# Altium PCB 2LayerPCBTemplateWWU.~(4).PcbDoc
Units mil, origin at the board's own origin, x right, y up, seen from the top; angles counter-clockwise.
Board outline 958.19 x 1191.13 mil, 2 copper layers (Top Layer, Bottom Layer); 9 components, 9 nets, 39 pads, 16 vias.
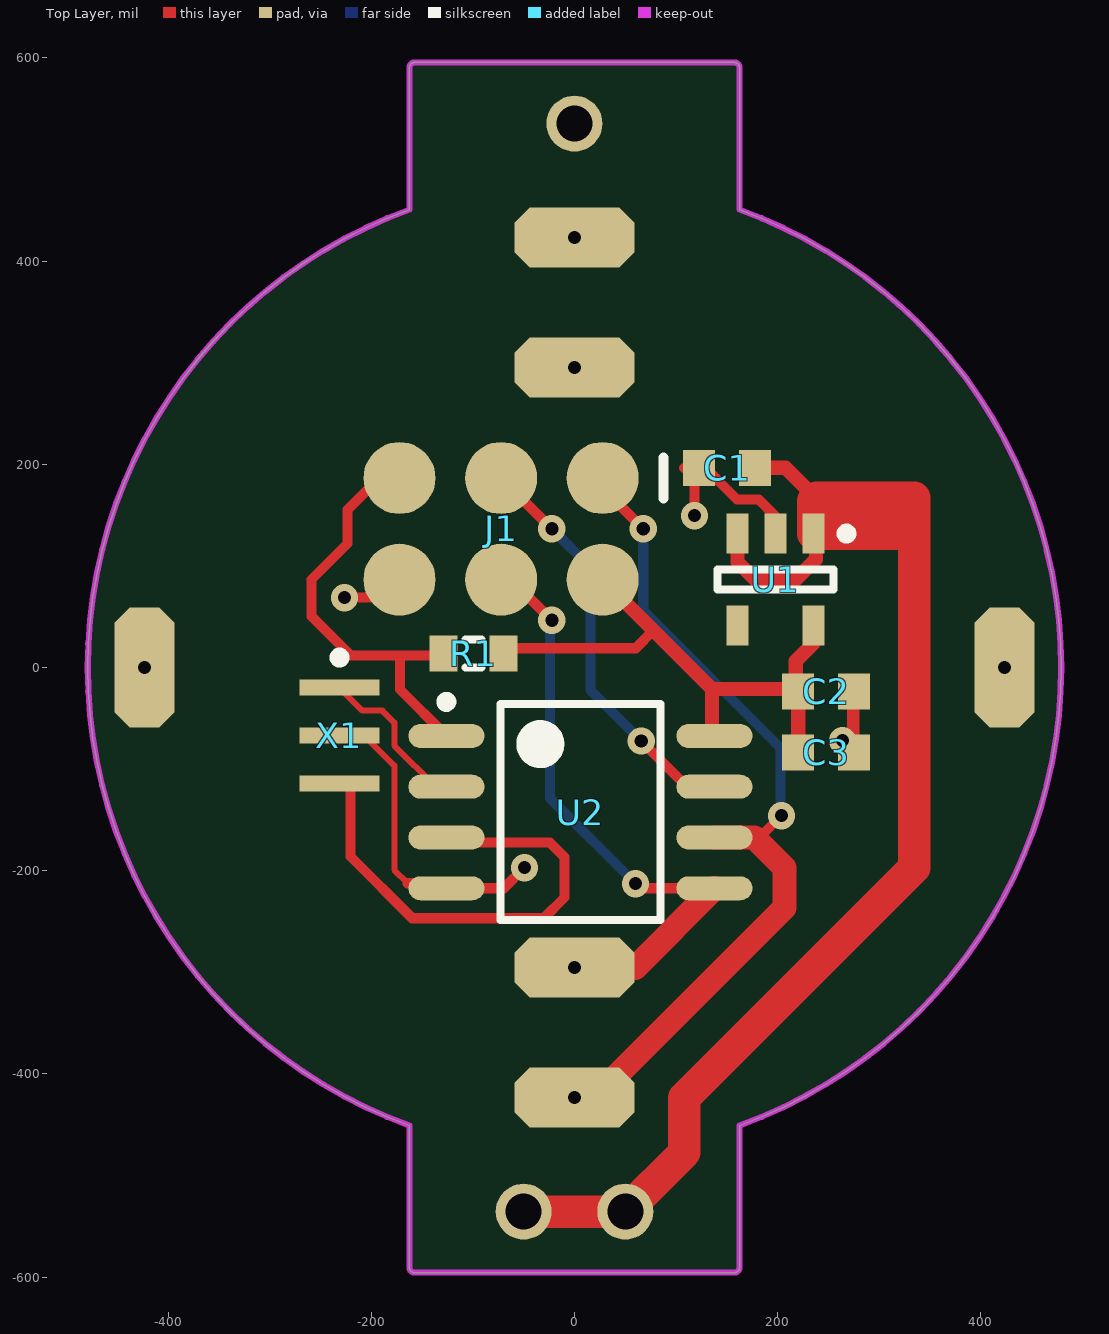
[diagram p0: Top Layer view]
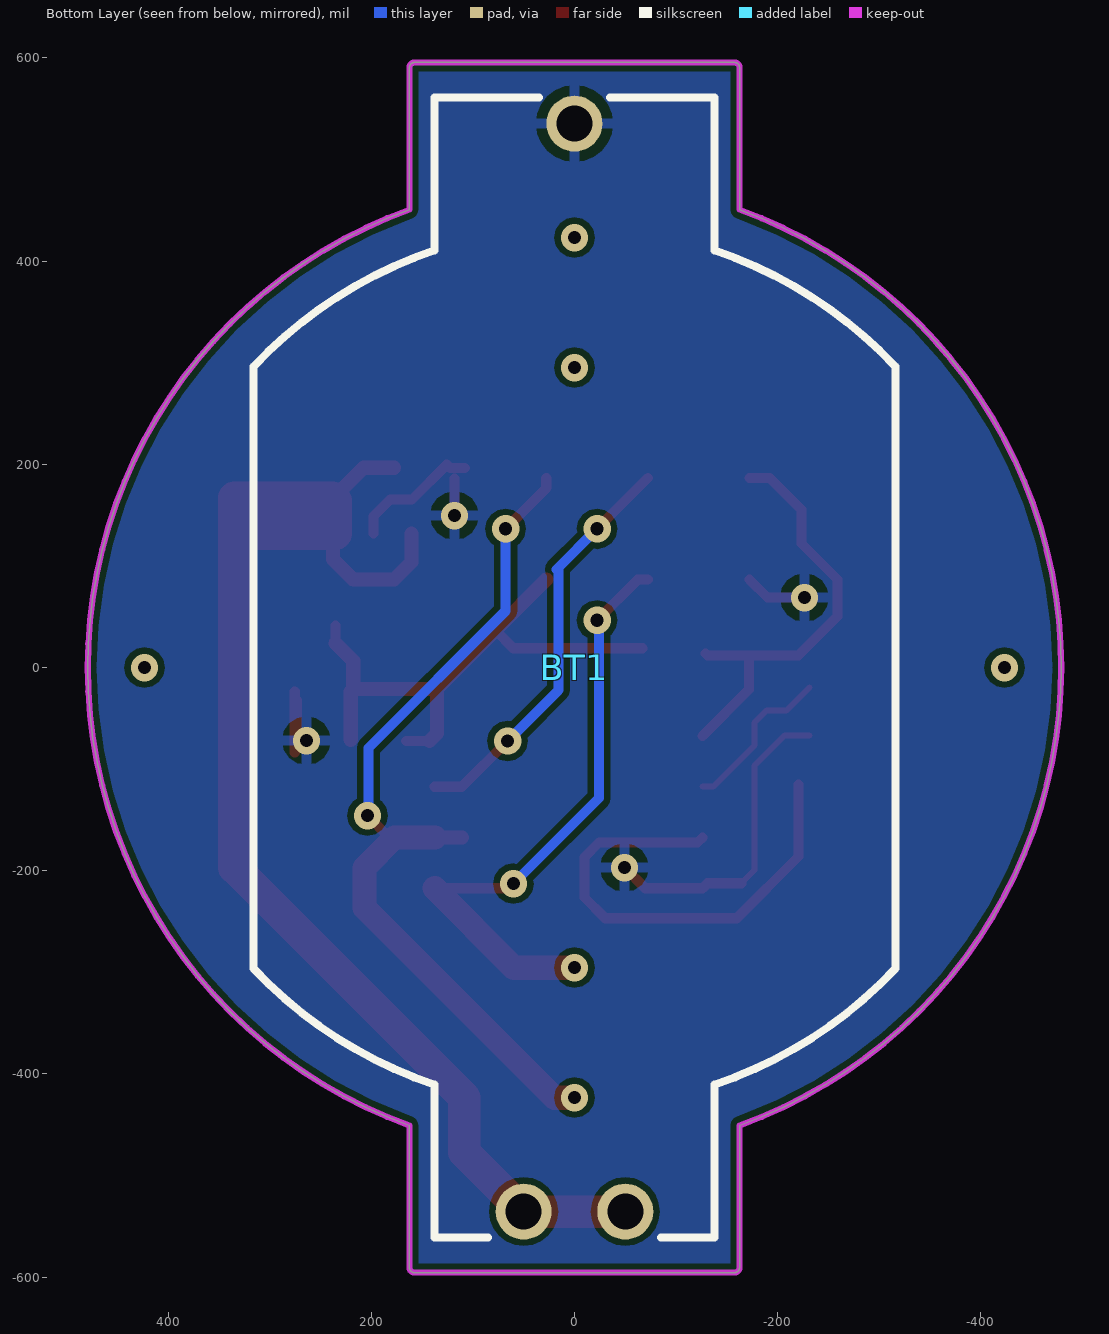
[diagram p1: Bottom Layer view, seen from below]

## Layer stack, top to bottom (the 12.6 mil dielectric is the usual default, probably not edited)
Top Solder: solder mask 0.4, Solder Resist, Dk 3.5
Top Layer: signal copper 1.4
Dielectric 1: dielectric 12.6, FR-4, Dk 4.8
Bottom Layer: signal copper 1.4
Bottom Solder: solder mask 0.4, Solder Resist, Dk 3.5

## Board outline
-162.5,-450.69 cw(c0,0) -479.09,0 cw(c0,0) -162.5,450.69 -162.5,590.55 cw(c-157.48,590.55) -157.48,595.57 157.48,595.57 cw(c157.48,590.55) 162.5,590.55 162.5,450.69 cw(c0,0) 479.09,0 cw(c0,0) 162.5,-450.69 162.5,-590.55 cw(c157.48,-590.55) 157.48,-595.57 -157.48,-595.57 cw(c-157.48,-590.55) -162.5,-590.55

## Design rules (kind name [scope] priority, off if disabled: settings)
Clearance [All] p1: gap=6
HoleSize [All] p1: absolutevalues=TRUE maxlimit=125 minlimit=13 maxpercent=80.000 minpercent=20.000
MinimumSolderMaskSliver [All] p1: minsoldermaskwidth=1
PolygonConnect [All] p1: connectstyle=Relief reliefconductorwidth=10 reliefentries=4 polygonreliefangle="90 Angle" airgapwidth=10
RoutingVias [All] p1: holewidth=13 width=20 viastyle="Through Hole" minholewidth=13 minwidth=20 maxholewidth=125 maxwidth=250
SilkToSilkClearance [All] p1: silktosilkclearance=4
SilkToSolderMaskClearance [IsPad] p1: minsilkscreentomaskgap=6 clearancetoexposedcopper=TRUE
SolderMaskExpansion [All] p1: expansion=4
UnpouredPolygon [All] p1: allowunpoured=FALSE
Width [All] p1: maxlimit=500 minlimit=6 preferedwidth=25
25 further rules are at their usual default settings.

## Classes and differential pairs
component class BSheetSchematicTemplateWWU: C1 C2 C3 J1 R1 U1 U2 X1

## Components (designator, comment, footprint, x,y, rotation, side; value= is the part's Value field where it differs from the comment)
BT1 "HU2032-LF" RENA-HU2032-LF_V 0,0 r90 bottom
C1 "Cap Semi" 1608[0603] 150.2,196.57 r0 top
C2 "Cap Semi" 1608[0603] 247.76,-23.43 r180 top
C3 "Cap Semi" 1608[0603] 247.76,-83.43 r180 top
J1 "AVR ISP" AVR_ISP 27.76,186.57 r270 top
R1 "Res3" J1-0603 -99.41,13.78 r0 top
U1 "NCP500SN33T1GOSCT" ONSC-SOT23-5_L 197.76,86.57 r270 top
U2 "ATtiny85V-10SH" 8S2_L 5.79,-142.24 r0 top
X1 "CSTCE8M00G55-R0" MURA-CSTCE_G_A-3_V -231.3,-66.93 r270 top

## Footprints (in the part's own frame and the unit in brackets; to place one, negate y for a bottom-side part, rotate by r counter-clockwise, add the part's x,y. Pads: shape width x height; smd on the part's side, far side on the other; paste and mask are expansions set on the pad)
8S2_L [mm] "SOP, 8-Leads, Body 5.3x5.3mm, Pitch 1.27mm, IPC High Density"
  oval 1.9x0.6 smd: 1(-3.35,1.905) 2(-3.35,0.635) 3(-3.35,-0.635) 4(-3.35,-1.905) 5(3.35,-1.905) 6(3.35,-0.635) 7(3.35,0.635) 8(3.35,1.905)
  silkscreen extent -3.47,-2.7 2,2.88, body extent -2.7,-2.68 2.7,2.68, height 2.16
1608[0603] [mm] "Chip Capacitor, Body 1.6x0.8mm, IPC High Density"
  rect 0.8x0.9 smd: 1(-0.7,0) 2(0.7,0)
  body extent -0.87,-0.48 0.87,0.48, height 1.3
AVR_ISP [mm] "AVR_ISP POGO CONNECTOR"
  round 1.8 smd: 1(0,0) 2(2.54,0) 3(0,-2.54) 4(2.54,-2.54) 5(0,-5.08) 6(2.54,-5.08)
  silkscreen extent -0.51,1.52 0.51,1.52
J1-0603 [mm] "Chip Resistor, Body 1.6x0.8mm, IPC High Density"
  rect 0.7x0.9 smd: 1(-0.75,0) 2(0.75,0)
  silkscreen extent -0.2,-0.35 0.2,0.35, body extent -0.85,-0.48 0.85,0.48, height 0.9
MURA-CSTCE_G_A-3_V [mm] "SMD, 3-Leads, Body 3.2x1.3mm, Pitch 1.2mm"
  rect 0.4x2 smd: 1(-1.2,0) 2(0,0) 3(1.2,0)
  silkscreen extent -2.07,-0.12 -1.83,0.13, body extent -1.6,-0.65 1.6,0.65, height 0.7
ONSC-SOT23-5_L [mm] "SOT23, 5-Leads, Body 2.90x1.6mm, Pitch 0.95mm, IPC High Density"
  rect 1x0.55 smd: 1(-1.15,0.95) 2(-1.15,0) 3(-1.15,-0.95) 4(1.15,-0.95) 5(1.15,0.95)
  silkscreen extent -1.27,-1.45 0.25,1.9, body extent -0.8,-1.45 0.8,1.45, height 1
RENA-HU2032-LF_V [mm] "THD, 3-Leads, Body 28.5x16.05mm"
  round 1.4 hole 0.9: 1(-13.6,1.27) 2(-13.6,-1.27) 3(13.6,0)
  silkscreen extent -14.25,-8.03 14.25,8.03, body extent -14.25,-8.03 14.25,8.03, height 5.35

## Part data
BT1: library part CMP-2000-06429-1, "Coin Cell Battery Holder, CR2032, Horizontal, -40 to 100 degC, 3-Pin THD, RoHS, Tray"
C1 C2 C3: "Capacitor (Semiconductor SIM Model)"
J1: library part AVR_ISP, "AVR ISP POGO CONNECTOR"
R1: "Resistor"
U1: library part CMP-0273-00001-2, "Fixed Low Drop Positive Voltage Regulator, 3.3V, 5-Pin TSOT-23, Tape and Reel"
U2: library part CMP-0093-00338-1, "8-bit AVR Microcontroller, 10MHz, 1.8-5.5V, 8K Flash, 512 Bytes EEPROM, 512 Bytes SRAM, Industrial Grade (-40°C to 85°C), 8-Lead SOIC, Pb-Free"
X1: library part CMP-2100-03620-1, "Ceramic Resonator, 8 MHz, +/- 0.5%, -20 to 80 degC, 3-Pin SMD, RoHS, Tape and Reel"

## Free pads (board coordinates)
  oct 59.06x118.11 smd: 0(-423.23,0) 0(423.23,0)
  oct 118.11x59.06 smd: 0(0,-423.23) 0(0,-295.28) 0(0,295.28) 0(0,423.23)

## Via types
v1: diameter 27, hole 13, Top Layer to Bottom Layer, tented both sides, 16 vias

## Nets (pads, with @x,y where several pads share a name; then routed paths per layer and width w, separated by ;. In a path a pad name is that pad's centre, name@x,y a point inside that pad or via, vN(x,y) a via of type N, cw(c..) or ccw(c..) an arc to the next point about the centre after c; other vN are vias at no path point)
GND: BT1.3 C1.1 C2.1 C3.1 J1.6 U1.2 U2.4 X1.2 | length 649.7
  Top Layer w6: X1.2 -206.69,-66.93 -177.17,-96.46 -177.17,-199.29 -164.21,-212.24
  Top Layer w10: v1(-226.38,68.9) -189.92,68.9 J1.6 ; -164.21,-212.24 -131.1,-212.24 U2.4 -69.61,-217.24 v1(-49.21,-196.85) ; C1.1@107.76,196.57 C1.1 125.69,199.62 159.96,165.35 181.42,165.35 197.76,149.02 U1.2 ; v1(118.11,149.61) C1.1@118.11,186.22 ; v1(263.78,-71.85) 273.35,-71.85 C2.1@273.35,-32.24 ; C3.1 C2.1
MISO: J1.1 pad.0@0,-423.23 U2.6 | length 872.4
  Top Layer w10: J1.1 27.76,176.57 v1(67.76,136.57) ; 177.09,-167.24 182.17,-167.24 v1(203.74,-145.67)
  Top Layer w14: U2.6@110.79,-167.24 U2.6
  Top Layer w24: v1(0,-423.23) 19.69,-423.23 206.69,-236.22 206.69,-196.85 177.09,-167.24 U2.6
  Bottom Layer w10: v1(67.76,136.57) 67.76,55.79 202.76,-79.21 202.76,-144.69 v1(203.74,-145.67)
MOSI: J1.4 pad.0@0,-295.28 U2.5 | length 610.2
  Top Layer w10: J1.4 -62.24,86.57 v1(-22.24,46.57) ; v1(60.04,-212.6) 64.69,-217.24 U2.5
  Top Layer w24: v1(0,-295.28) 59.65,-295.28 U2.5
  Bottom Layer w10: v1@-24.21,46.57 -24.21,-128.35 v1(60.04,-212.6)
RST: J1.5 R1.1 U2.1 | length 428.4
  Top Layer w10: J1.5 -192.24,186.57 -223.43,155.39 -223.43,122.05 -258.86,86.61 -258.86,50.38 -220.29,11.81 -171.69,11.81 ; R1.1 -130.91,11.81 -171.69,11.81 ; U2.1 -171.69,-21.65 -171.69,11.81
SCK: J1.3 U2.7 | length 407.2
  Top Layer w10: J1.3 v1(-22.24,136.57) ; v1(65.79,-72.24) 110.79,-117.24 U2.7
  Bottom Layer w10: v1(-22.24,136.57) 17.76,96.57 ; 15.79,96.46 15.79,-22.24 v1(65.79,-72.24)
VCC: C2.2 C3.2 J1.2 R1.2 U1.5 U2.8 | length 584.4
  Top Layer w10: R1.2@-66.93,19.07 60.25,19.07 77.76,36.57 ; U2.8@142.68,-72.24 U2.8@165.79,-72.24 ; C2.2@217.76,-20.98 C2.2 ; U1.5@235.16,23.98 U1.5
  Top Layer w14: J1.2 77.76,36.57 135.32,-20.98 ; U2.8@142.68,-72.24 U2.8 135.32,-64.88 135.32,-20.98 ; C3.2@220.2,-70.98 C2.2 ; U1.5@235.16,23.98 217.76,6.57 217.76,-20.98 135.32,-20.98
VIN: BT1.1 BT1.2 C1.2 U1.1 U1.3 | length 1502
  Top Layer w14: U1.3 160.35,103.98 177.76,86.57 217.76,86.57 237.76,106.57 237.76,131.85 237.76,157.48 237.76,163.98 ; C1.2 207.76,196.57 237.76,166.57
  Top Layer w32: BT1.2 BT1.1 108.27,-477.17 108.27,-423.23 334.65,-196.85 334.65,167.32 238.5,167.32 237.76,166.57 237.76,163.98 ; 235.16,163.98 U1.1 237.76,131.85 318.86,131.85 324.8,137.8 324.8,157.48 237.76,157.48
XTAL1: U2.2 X1.1 | length 158.9
  Top Layer w6: X1.1 -208.66,-42.32 -188.98,-42.32 -177.17,-54.13 -177.17,-76.77 -136.69,-117.24 U2.2
XTAL2: U2.3 X1.3 | length 479.1
  Top Layer w10: X1.3@-220.47,-115.16 -220.47,-185.98 -159.71,-246.74 -30.21,-246.74 -9.84,-226.38 -9.84,-186.61 -24.21,-172.24 -121.1,-172.24 U2.3
pads on no net: U1.4
copper on no net:
  other v1: -423.23,0 423.23,0 0,295.28 0,423.23

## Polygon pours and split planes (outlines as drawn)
GND on Bottom Layer "GND_BTTM" (solid, pour order 4): -162.5,-450.69 cw(c0,0) -479.09,0 cw(c0,0) -162.5,450.69 -162.5,590.55 cw(c-157.48,590.55) -157.48,595.57 157.48,595.57 cw(c157.48,590.55) 162.5,590.55 162.5,450.69 cw(c0,0) 479.09,0 cw(c0,0) 162.5,-450.69 162.5,-590.55 cw(c157.48,-590.55) 157.48,-595.57 -157.48,-595.57 cw(c-157.48,-590.55) -162.5,-590.55

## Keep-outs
Keep-Out Layer:
  the board outline again, w6

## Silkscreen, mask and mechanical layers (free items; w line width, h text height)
Mechanical 19:
  circle w10: c0,0 r324.8
  circle w10: c0,0 r393.58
